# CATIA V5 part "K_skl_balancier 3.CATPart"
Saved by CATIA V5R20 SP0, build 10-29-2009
Part number: skl_balancier 3
Publications: "longueur axe pivot", "liaison 3/5", "liaison 3/18 sur 3", "liaison 3/10", "Plan.00", "Droite.1", "Droite.2", "Droite.3", "Droite.4", "Droite.5"
Bounding box of the stored display mesh (mm): x 0 to 150, y -720 to 0, z 0 to 0
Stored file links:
  G:\Khaled_CFAO_2011\SIL\SIL_GR2\mdardier\Khaled\CAD_ThinkMOTION\K_skl_balancier 3.CATPart
  G:\Khaled_CFAO_2011\SIL\SIL_GR2\mdardier\Khaled\CAD_ThinkMOTION\K_skl_ass_tandem.CATProduct
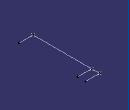
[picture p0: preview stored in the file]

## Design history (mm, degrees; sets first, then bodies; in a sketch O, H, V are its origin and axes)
External parameters (linked from other documents)
  `External.longueur axe pivot` = 150 mm
Set1
  Point1 "liaison 3/5": linked copy from another document
  Point2 "liaison 3/18 sur 3": linked copy from another document
  Point3 "liaison 3/10": linked copy from another document
  Plane1 "Plan.00": linked copy from another document
Set2
  Line1: type PtPt, FirstPoint Point1, SecondPoint Point2
  Line2: type PtPt, FirstPoint Point2, SecondPoint Point3
  Line3: type Normal, RefPoint Point1, RefSkin Plane1, Start 0, End 150 {= `External.longueur axe pivot`}
  Line4: type Normal, RefPoint Point2, RefSkin Plane1, Start 0, End 150 {= `External.longueur axe pivot`}
  Line5: type Normal, RefPoint Point3, RefSkin Plane1, Start 0, End 150 {= `External.longueur axe pivot`}
Body1 (main body)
